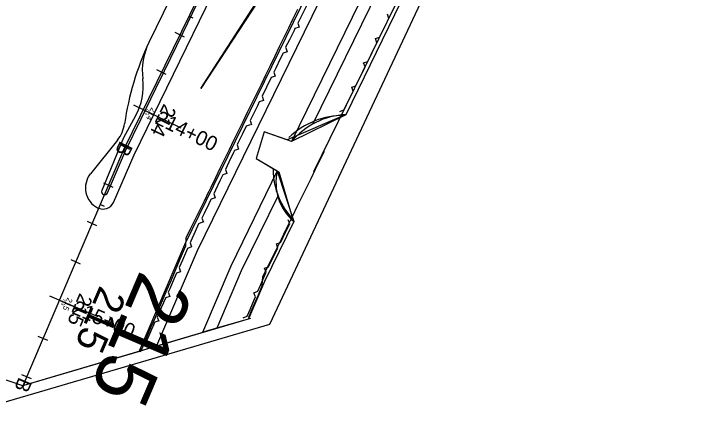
# Model space of a CAD drawing. Extents: x 1823824 to 1861612, y 706975 to 726130.
# Drawn here: x 1824482.5 to 1824817.1, y 711409.2 to 711601.3 of the extents above; entities that cross this region are included whole.
import ezdxf

# ---------------------------------------------------------------- set-up
doc = ezdxf.new("R2010")
doc.units = 0
for name, color, linetype in [('DR_X_Flood_Boundary', 7, 'Continuous'), ('GE_X_CL_10', 7, 'Continuous'), ('GE_X_CL_100', 7, 'Continuous'), ('GE_X_CL_20', 7, 'Continuous'), ('GE_X_CL_200', 7, 'Continuous'), ('GE_X_CL_50', 7, 'Continuous'), ('RW_X_Esmt_FL', 7, 'Continuous'), ('SC_Scratch1', 7, 'Continuous'), ('SC_Scratch5', 7, 'Continuous'), ('SC_Scratch6', 7, 'Continuous')]:
    doc.layers.add(name, color=color, linetype=linetype)

msp = doc.modelspace()

# ---------------------------------------------------------------- linework, layer by layer
at = {"layer": 'DR_X_Flood_Boundary'}
for p, q in [((1824589.41, 711646.8), (1824535.27, 711536.02)), ((1824535.27, 711536.02), (1824486.83, 711422.71)), ((1824486.83, 711422.71), (1824451.24, 711434.9))]:
    msp.add_line(p, q, dxfattribs=at)
at = {"layer": 'GE_X_CL_10'}
for p, q in [((1824566.67, 711600.27), (1824567.57, 711599.84)), ((1824544.72, 711555.35), (1824545.62, 711554.91)), ((1824524.07, 711509.83), (1824524.99, 711509.44)), ((1824504.42, 711463.86), (1824505.34, 711463.46))]:
    msp.add_line(p, q, dxfattribs=at)
at = {"layer": 'GE_X_CL_100'}
for p, q in [((1824544.72, 711555.35), (1824553.7, 711550.96)), ((1824504.42, 711463.86), (1824513.61, 711459.93))]:
    msp.add_line(p, q, dxfattribs=at)
at = {"layer": 'GE_X_CL_20'}
for p, q in [((1824566.67, 711600.27), (1824568.47, 711599.4)), ((1824544.72, 711555.35), (1824546.52, 711554.47)), ((1824524.07, 711509.83), (1824525.91, 711509.05)), ((1824504.42, 711463.86), (1824506.26, 711463.07))]:
    msp.add_line(p, q, dxfattribs=at)
at = {"layer": 'GE_X_CL_200'}
for p, q in [((1824544.72, 711555.35), (1824562.69, 711546.57)), ((1824504.42, 711463.86), (1824522.81, 711456))]:
    msp.add_line(p, q, dxfattribs=at)
at = {"layer": 'GE_X_CL_50'}
for p, q in [((1824544.72, 711555.35), (1824549.21, 711553.16)), ((1824504.42, 711463.86), (1824509.02, 711461.89))]:
    msp.add_line(p, q, dxfattribs=at)
at = {"layer": 'RW_X_Esmt_FL'}
for p, q in [((1824605.52, 711452.44), (1824689.22, 711630.44)), ((1824458.62, 711409.24), (1824605.52, 711452.44))]:
    msp.add_line(p, q, dxfattribs=at)
at = {"layer": 'SC_Scratch1'}
for p, q in [((1824662.7, 711599.12), (1824662.03, 711601.12)), ((1824619.59, 711594.93), (1824617.59, 711594.26)), ((1824618.92, 711596.93), (1824619.59, 711594.93)), ((1824656.31, 711589.47), (1824658.3, 711590.15)), ((1824656.99, 711587.47), (1824656.31, 711589.47)), ((1824613.1, 711585.33), (1824613.77, 711583.33)), ((1824613.84, 711583.09), (1824611.85, 711582.4)), ((1824650.59, 711577.82), (1824652.58, 711578.5)), ((1824651.27, 711575.83), (1824650.59, 711577.82)), ((1824608.14, 711571.43), (1824606.15, 711570.74)), ((1824607.46, 711573.42), (1824608.14, 711571.43)), ((1824644.87, 711566.17), (1824646.86, 711566.85)), ((1824645.55, 711564.18), (1824644.87, 711566.17)), ((1824601.76, 711561.76), (1824602.44, 711559.77)), ((1824602.44, 711559.77), (1824600.45, 711559.09)), ((1824639.15, 711554.52), (1824641.14, 711555.2)), ((1824641.16, 711552.5), (1824613.86, 711540.79)), ((1824642.05, 711552.94), (1824615.99, 711540.02)), ((1824596.1, 711548.11), (1824594.11, 711547.41)), ((1824596.06, 711550.1), (1824596.74, 711548.11)), ((1824602.83, 711544.78), (1824598.95, 711531.98)), ((1824615.99, 711540.02), (1824602.83, 711544.78)), ((1824532.3, 711540.73), (1824519.26, 711524.53)), ((1824589.78, 711538.4), (1824590.48, 711536.41)), ((1824590.48, 711536.41), (1824588.49, 711535.71)), ((1824598.95, 711531.98), (1824609.12, 711525.96)), ((1824584.85, 711524.72), (1824582.87, 711524.02)), ((1824584.16, 711526.7), (1824584.85, 711524.72)), ((1824609.12, 711525.96), (1824617.02, 711501.67)), ((1824616.74, 711502.53), (1824610.06, 711525.4)), ((1824578.54, 711515.01), (1824579.23, 711513.02)), ((1824579.23, 711513.02), (1824577.25, 711512.32)), ((1824573.18, 711501.29), (1824571.22, 711500.54)), ((1824572.9, 711503.32), (1824573.6, 711501.33)), ((1824615.06, 711500.55), (1824614.38, 711502.54)), ((1824567.17, 711491.4), (1824567.92, 711489.43)), ((1824608.67, 711490.89), (1824610.66, 711491.57)), ((1824609.35, 711488.9), (1824608.67, 711490.89)), ((1824567.92, 711489.43), (1824565.96, 711488.67)), ((1824562.66, 711477.57), (1824560.7, 711476.81)), ((1824561.91, 711479.53), (1824562.66, 711477.57)), ((1824602.95, 711479.25), (1824604.94, 711479.93)), ((1824603.73, 711477.31), (1824602.97, 711479.27)), ((1824556.65, 711467.67), (1824557.4, 711465.71)), ((1824597.76, 711467.39), (1824599.72, 711468.16)), ((1824598.6, 711465.44), (1824597.83, 711467.4)), ((1824557.4, 711465.71), (1824555.44, 711464.95)), ((1824486.3, 711422.74), (1824595.3, 711455)), ((1824552.17, 711454.03), (1824550.2, 711453.28)), ((1824551.38, 711455.81), (1824552.13, 711453.85)), ((1824592.67, 711455.5), (1824594.62, 711456.27)), ((1824546.14, 711444.14), (1824546.89, 711442.18))]:
    msp.add_line(p, q, dxfattribs=at)
for points in [[(1825105.72, 712238.1), (1825041.58, 712175.28), (1825012.05, 712142.98), (1824928.03, 712058.8), (1824867.42, 711988.62), (1824838.82, 711954.42), (1824791.58, 711892.69), (1824765.73, 711856.76), (1824735.96, 711811.35), (1824706.1, 711762.93), (1824677.47, 711714.29), (1824651.68, 711665.89), (1824630.67, 711625.89), (1824564.54, 711490.46), (1824542.7, 711439.44)], [(1825110.13, 712232.99), (1825046.42, 712170.6), (1825016.92, 712138.33), (1824932.97, 712054.22), (1824872.55, 711984.27), (1824844.08, 711950.22), (1824796.99, 711888.68), (1824771.28, 711852.95), (1824741.64, 711807.74), (1824711.87, 711759.46), (1824683.34, 711710.99), (1824657.63, 711662.75), (1824636.68, 711622.85), (1824570.66, 711487.65), (1824551.08, 711441.92)], [(1825121.76, 712219.53), (1825059.19, 712158.26), (1825029.76, 712126.06), (1824945.98, 712042.13), (1824886.07, 711972.77), (1824857.94, 711939.13), (1824811.24, 711878.1), (1824785.91, 711842.89), (1824756.62, 711798.22), (1824727.07, 711750.3), (1824698.83, 711702.31), (1824673.32, 711654.44), (1824652.51, 711614.83), (1824615.99, 711540.02)], [(1825125.32, 712215.32), (1825063.14, 712154.44), (1825033.74, 712122.26), (1824950.02, 712038.39), (1824890.27, 711969.21), (1824862.23, 711935.69), (1824815.66, 711874.82), (1824790.44, 711839.78), (1824761.26, 711795.26), (1824731.78, 711747.46), (1824703.63, 711699.63), (1824678.18, 711651.87), (1824657.42, 711612.34), (1824626.24, 711548.48)], [(1825133.34, 712206.03), (1825071.96, 712145.93), (1825042.6, 712113.8), (1824959, 712030.04), (1824899.6, 711961.27), (1824871.8, 711928.03), (1824825.5, 711867.52), (1824800.54, 711832.84), (1824771.6, 711788.69), (1824742.28, 711741.14), (1824714.32, 711693.64), (1824689.01, 711646.14), (1824668.35, 711606.81), (1824642.05, 711552.94)], [(1824736.46, 711815.76), (1824572.41, 711565.5), (1824785.18, 711894.95)], [(1824527.53, 711515.37), (1824536.18, 711535.58), (1824536.18, 711535.58), (1824543.71, 711551), (1824550.79, 711565.51), (1824554.97, 711574.06), (1824563.89, 711592.34), (1824570.67, 711606.23), (1824577.83, 711620.9), (1824590.72, 711647.29), (1824589.41, 711646.8), (1824588.91, 711645.84), (1824578.51, 711651.3), (1824547.37, 711587.57)], [(1824530.46, 711510.76), (1824540.26, 711533.7), (1824596.86, 711649.6), (1824590.72, 711647.29)], [(1824595.44, 711455.71), (1824596.11, 711457.27), (1824598.07, 711461.86), (1824600.04, 711466.46), (1824601.91, 711470.84), (1824601.91, 711470.94), (1824602.15, 711475.08), (1824604.45, 711479.75), (1824606.65, 711484.24), (1824608.86, 711488.72), (1824611.06, 711493.21), (1824613.26, 711497.7), (1824613.34, 711497.86), (1824614.33, 711499.88), (1824616.52, 711504.37), (1824618.72, 711508.86), (1824620.92, 711513.35), (1824623.11, 711517.84), (1824625.31, 711522.34), (1824627.5, 711526.83), (1824629.7, 711531.32), (1824631.59, 711535.19), (1824626.65, 711525.69), (1824665.92, 711605.67)], [(1824623.41, 711605.86), (1824621.63, 711602.31), (1824619.39, 711597.85), (1824618.92, 711596.93)], [(1824618.85, 711603.41), (1824616.65, 711598.91), (1824614.46, 711594.42), (1824612.26, 711589.93), (1824610.07, 711585.44), (1824607.87, 711580.94), (1824605.68, 711576.45), (1824603.48, 711571.96), (1824601.28, 711567.47), (1824599.09, 711562.98), (1824596.89, 711558.48), (1824594.7, 711553.99), (1824592.5, 711549.5), (1824590.31, 711545.01), (1824588.11, 711540.52), (1824585.92, 711536.02), (1824583.72, 711531.53), (1824581.52, 711527.04), (1824579.33, 711522.55), (1824577.13, 711518.05), (1824576.15, 711516.03), (1824576.1, 711515.95), (1824573.9, 711511.46)], [(1824658.3, 711590.15), (1824662.7, 711599.12)], [(1824617.59, 711594.26), (1824617.14, 711593.38), (1824614.9, 711588.91), (1824613.1, 711585.33)], [(1824652.58, 711578.5), (1824656.99, 711587.47)], [(1824611.85, 711582.4), (1824610.52, 711579.69), (1824608.33, 711575.2), (1824607.46, 711573.42)], [(1824646.86, 711566.85), (1824651.27, 711575.83)], [(1824606.15, 711570.74), (1824606.13, 711570.71), (1824603.94, 711566.22), (1824601.76, 711561.76)], [(1824641.14, 711555.2), (1824645.55, 711564.18)], [(1824600.45, 711559.09), (1824599.55, 711557.23), (1824597.35, 711552.74), (1824596.06, 711550.1)], [(1824541, 711552.32), (1824535.16, 711541.89), (1824524.77, 711516.55)], [(1824594.11, 711547.41), (1824592.34, 711543.73), (1824590.18, 711539.22), (1824589.78, 711538.4)], [(1824613.86, 711540.79), (1824602.83, 711544.78), (1824598.95, 711531.98), (1824610.06, 711525.4)], [(1824588.49, 711535.71), (1824588.01, 711534.72), (1824585.84, 711530.21), (1824584.16, 711526.7)], [(1824609.12, 711525.96), (1824586.81, 711480.26), (1824573.19, 711448.46)], [(1824582.87, 711524.02), (1824581.51, 711521.2), (1824579.35, 711516.69), (1824578.54, 711515.01)], [(1824609.33, 711513.85), (1824591.81, 711477.97), (1824580.04, 711450.49)], [(1824573.9, 711511.46), (1824571.7, 711506.98), (1824569.49, 711502.49), (1824567.29, 711498), (1824565.17, 711493.69), (1824564.94, 711489.86), (1824563.94, 711487.34), (1824561.97, 711482.74), (1824560.01, 711478.14), (1824558.04, 711473.54), (1824556.08, 711468.94), (1824554.11, 711464.35), (1824552.14, 711459.75), (1824550.18, 711455.15), (1824548.21, 711450.55), (1824546.25, 711445.96), (1824544.28, 711441.36), (1824543.24, 711438.93)], [(1824577.25, 711512.32), (1824577.18, 711512.18), (1824576.21, 711510.15), (1824576.17, 711510.07), (1824573.99, 711505.57), (1824572.9, 711503.32)], [(1824571.22, 711500.54), (1824569.56, 711496.8), (1824567.54, 711492.23), (1824567.17, 711491.4)], [(1824617.02, 711501.67), (1824602.95, 711472.87), (1824595.3, 711455)], [(1824610.66, 711491.57), (1824610.89, 711492.04), (1824613.1, 711496.53), (1824613.18, 711496.69), (1824614.16, 711498.71), (1824615.06, 711500.55)], [(1824565.96, 711488.67), (1824565.51, 711487.66), (1824563.48, 711483.09), (1824561.91, 711479.53)], [(1824604.94, 711479.93), (1824606.48, 711483.07), (1824608.69, 711487.56), (1824609.35, 711488.9)], [(1824599.72, 711468.16), (1824601.12, 711471.36), (1824603.13, 711475.94), (1824603.73, 711477.31)], [(1824560.7, 711476.81), (1824559.43, 711473.95), (1824557.4, 711469.38), (1824556.65, 711467.67)], [(1824555.44, 711464.95), (1824555.38, 711464.81), (1824554.47, 711462.75), (1824554.43, 711462.66), (1824552.39, 711458.1), (1824551.38, 711455.81)], [(1824594.62, 711456.27), (1824596.02, 711459.48), (1824598.01, 711464.06), (1824598.6, 711465.44)], [(1824486.3, 711422.74), (1824542.33, 711439.32), (1824549.05, 711441.31), (1824572.39, 711448.22), (1824576.19, 711449.47), (1824596.36, 711455.31)], [(1824550.2, 711453.28), (1824550.14, 711453.13), (1824549.23, 711451.08), (1824549.19, 711450.99), (1824547.16, 711446.43), (1824546.14, 711444.14)]]:
    msp.add_lwpolyline(points, dxfattribs=at)
for centre, radius, start, end in [((1824575.09, 711574.03), 30.85, 153.9731, 187.1461), ((1824515.54, 711566.57), 29.17, 330.7708, 7.1461), ((1824643.67, 711516.93), 36.05, 92.5739, 140.1686), ((1824519.65, 711550.91), 16.23, 321.175, 351.7708), ((1824527.61, 711517.8), 10.72, 141.1748, 243.1036), ((1824633.06, 711520.32), 24.59, 166.7374, 229.2868), ((1824526.15, 711515.96), 1.5, 156.8967, 336.8265)]:
    msp.add_arc(centre, radius, start, end, dxfattribs=at)
for centre, major_axis, ratio, start_param, end_param in [((1824672.69, 711528.73), (-10.15, -138.35), 0.997669, 4.347407, 4.641833), ((1824635.26, 711519.42), (-25.46, -24.79), 0.86106, 3.836016, 4.685508), ((1824639.97, 711528.75), (-7.93, -34.92), 0.915217, 4.979071, 5.743146), ((1824525.22, 711513.76), (1.91, -5.85), 0.958798, 5.526957, 7.039178)]:
    msp.add_ellipse(centre, major_axis=major_axis, ratio=ratio, start_param=start_param, end_param=end_param, dxfattribs=at)
at = {"layer": 'SC_Scratch5'}
for points in [[(1824564.53, 711590.19), (1824560.04, 711592.39)], [(1824555.75, 711572.22), (1824551.25, 711574.42)], [(1824549.21, 711553.16), (1824540.23, 711557.55)], [(1824538.18, 711536.29), (1824533.69, 711538.48)], [(1824530.3, 711518.04), (1824525.71, 711520.01)], [(1824522.44, 711499.65), (1824517.84, 711501.62)], [(1824514.58, 711481.26), (1824509.98, 711483.23)], [(1824509.02, 711461.89), (1824499.82, 711465.82)], [(1824498.85, 711444.48), (1824494.26, 711446.45)], [(1824490.99, 711426.09), (1824486.4, 711428.06)]]:
    msp.add_lwpolyline(points, dxfattribs=at)

# ---------------------------------------------------------------- texts
at = {"layer": 'GE_X_CL_10'}
for s, rotation, p in [('214', 243.9526, (1824546.7, 711555.99)), ('215', 246.8523, (1824506.37, 711464.61))]:
    msp.add_text(s, height=1.4, rotation=rotation, dxfattribs=at).set_placement(p)
at = {"layer": 'GE_X_CL_100'}
msp.add_text('215', height=14, rotation=246.8523, dxfattribs=at).set_placement((1824523.95, 711471.39))
at = {"layer": 'GE_X_CL_20'}
for s, rotation, p in [('214', 243.9526, (1824548.68, 711556.63)), ('215', 246.8523, (1824508.32, 711465.36))]:
    msp.add_text(s, height=2.8, rotation=rotation, dxfattribs=at).set_placement(p)
at = {"layer": 'GE_X_CL_200'}
msp.add_text('215', height=28, rotation=246.8523, dxfattribs=at).set_placement((1824543.48, 711478.92))
at = {"layer": 'GE_X_CL_50'}
for s, rotation, p in [('214', 243.9526, (1824554.63, 711558.54)), ('215', 246.8523, (1824514.18, 711467.62))]:
    msp.add_text(s, height=7, rotation=rotation, dxfattribs=at).set_placement(p)
at = {"layer": 'SC_Scratch5'}
for s, rotation, p in [('214+00', 333.9526, (1824549.92, 711548.92)), ('215+00', 336.8523, (1824509.94, 711457.69))]:
    msp.add_text(s, height=7, rotation=rotation, dxfattribs=at).set_placement(p)
at = {"layer": 'SC_Scratch6'}
for rotation, p in [(243.9526, (1824533.66, 711540.7)), (246.8523, (1824484.98, 711427.3))]:
    msp.add_text('B', height=7, rotation=rotation, dxfattribs=at).set_placement(p)

doc.saveas('drawing.dxf')
